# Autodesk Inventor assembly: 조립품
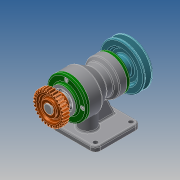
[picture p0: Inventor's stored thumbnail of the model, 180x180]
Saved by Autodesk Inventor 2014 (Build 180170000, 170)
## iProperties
Created: 2019-01
Part Number: 조립품
Document SubType Name: Assembly
Designer: kb542-15
Author: kb542-15
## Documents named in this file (15)
- C:\Users\kb542-15\Desktop\새 폴더 (3)\조립품.iam
- C:\Users\kb542-15\Desktop\새 폴더 (3)\V-벨트풀리.ipt
- C:\Users\kb542-15\Desktop\새 폴더 (3)\뒤커버.ipt
- C:\Users\kb542-15\Desktop\새 폴더 (3)\멈춤나사 M3.ipt
- C:\Users\kb542-15\Desktop\새 폴더 (3)\베어링 6203.ipt
- C:\Users\kb542-15\Desktop\새 폴더 (3)\베어링 6205.ipt
- C:\Users\kb542-15\Desktop\새 폴더 (3)\본체.ipt
- C:\Users\kb542-15\Desktop\새 폴더 (3)\볼트 M4.ipt
- C:\Users\kb542-15\Desktop\새 폴더 (3)\스퍼기어.ipt
- C:\Users\kb542-15\Desktop\새 폴더 (3)\앞커버.ipt
- C:\Users\kb542-15\Desktop\새 폴더 (3)\오일 실 17 30 8.ipt
- C:\Users\kb542-15\Desktop\새 폴더 (3)\오일 실 25 38 8.ipt
- C:\Users\kb542-15\Desktop\새 폴더 (3)\축.ipt
- C:\Users\kb542-15\Desktop\새 폴더 (3)\키 5 x 5 x 20.ipt
- C:\Users\kb542-15\Desktop\새 폴더 (3)\키 6 x 6 x 18.ipt
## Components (1 placed, 1 different names)
1. V-벨트풀리:1
